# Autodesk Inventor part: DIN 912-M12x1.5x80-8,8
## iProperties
Shininess: 64.0
Length Units: 11269
Angle Units: 11279
Time Units: 11290
Mass Units: 11283
Length Display Precision: 3
Angle Display Precision: 2
Compacted: True
Part Number: DIN 912-M12x1.5x80-8,8
Document SubType Name: Modeling
Created: 2005-02
Material: Par défaut
Designer: LEGERET Philippe
Catalog Web Link: www.traceparts.com
Description: Vis cylindrique hexagonale creuse DIN 912-M12x1.5x80-8,8
Density: 0.0
Volumn: 0.0
Area: 0.0
PropertySet Name: Model Information
Control State: 0
Master: False
Checked Out: False
Author: Trace Parts S.A.
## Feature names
1. Base1
